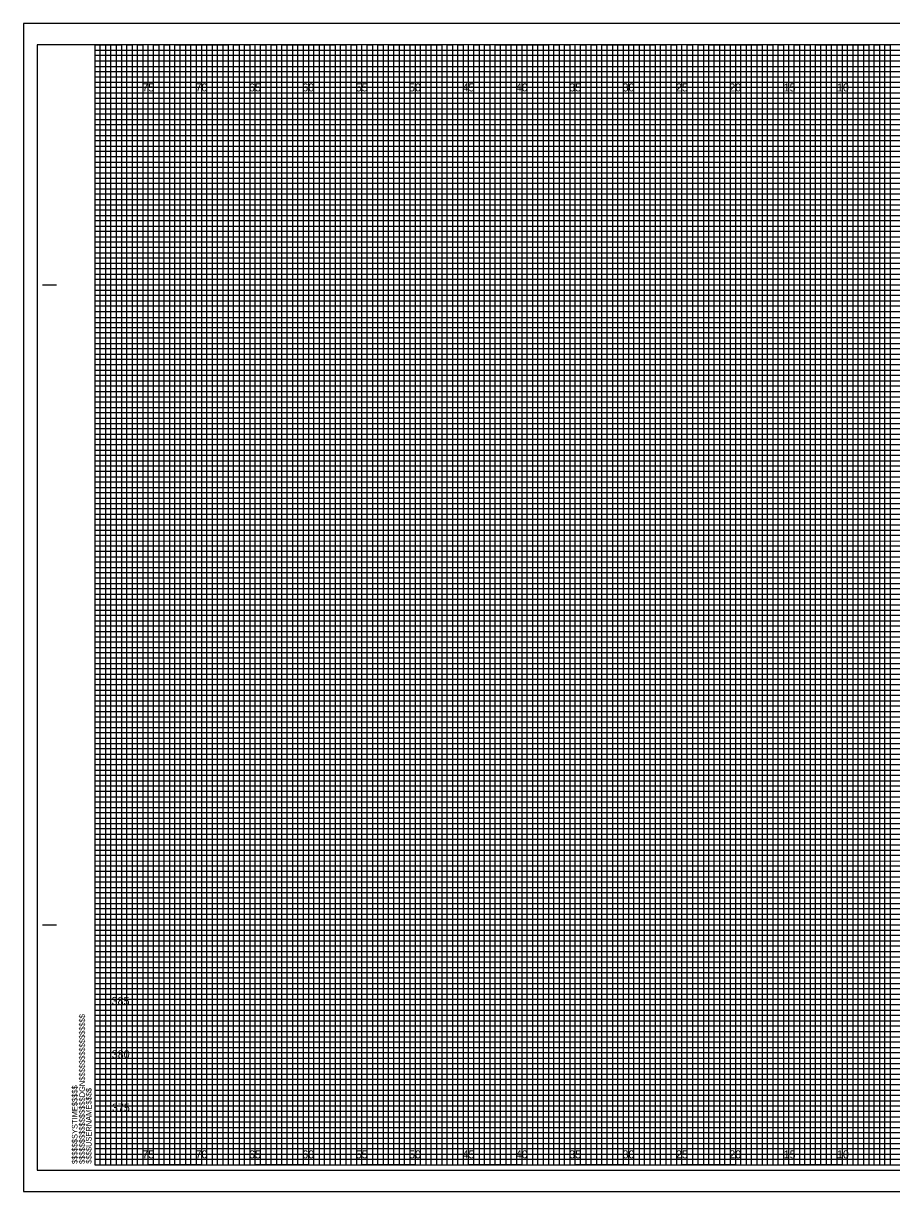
# Model space of a CAD drawing. Extents: x -7 to 162, y -2 to 217.
# Drawn here: x -6.7 to 74.6, y 107.5 to 217 of the extents above; entities that cross this region are included whole.
import ezdxf

# ---------------------------------------------------------------- set-up
doc = ezdxf.new("R2010")
doc.units = 0
for name, color, linetype in [('Exist Cross Section Cell', 7, 'Continuous'), ('Prop CMT Pvmt Course 1', 7, 'Continuous'), ('Prop CMT Pvmt Course 3', 7, 'Continuous'), ('Prop CMT Shld Paved Course 1', 7, 'Continuous'), ('Prop CMT Shld Paved Course 2', 7, 'Continuous'), ('Prop CMT Shld Paved Course 3', 7, 'Continuous'), ('Prop CMT Slope Grass', 7, 'Continuous'), ('Prop CMT Subgrade Earthwork', 7, 'Continuous'), ('Scratch_Level_3', 7, 'Continuous')]:
    doc.layers.add(name, color=color, linetype=linetype)

msp = doc.modelspace()

# ---------------------------------------------------------------- linework, layer by layer
at = {"layer": 'Prop CMT Pvmt Course 3'}
msp.add_lwpolyline([(-6.7, 107.5), (161.65, 107.5), (161.65, 217), (-6.7, 217)], close=True, dxfattribs=at)
at = {"layer": 'Prop CMT Shld Paved Course 1'}
for p, q in [((0, 214.5), (110.95, 214.5)), ((110.95, 213.99), (0, 213.99)), ((0, 213.99), (0, 213.5)), ((0, 213.5), (110.95, 213.5)), ((110.95, 212.94), (0, 212.94)), ((0, 212.94), (0, 212)), ((0, 212), (160, 212))]:
    msp.add_line(p, q, dxfattribs=at)
for points in [[(0, 211.5), (135, 211.5), (160, 211.5)], [(160, 211), (0, 211)], [(0, 210.5), (160, 210.5)], [(160, 209.5), (0, 209.5)], [(0, 209), (160, 209)], [(160, 208.5), (0, 208.49)], [(0, 208), (160, 208)], [(160, 207), (0, 207)], [(0, 206.5), (160, 206.5), (160, 206), (0, 206)], [(0, 205.5), (160, 205.5), (160, 204.5), (0, 204.5)], [(0, 204), (160, 204), (160, 203.5), (0, 203.5)], [(0, 203), (160, 203), (160, 202), (0, 202)], [(0, 201.5), (160, 201.5), (160, 201), (0, 201)], [(0, 200.5), (160, 200.5), (160, 199.5), (0, 199.5)], [(0, 199), (160, 199), (160, 198.5), (0, 198.5)], [(0, 198), (160, 198), (160, 196.97), (160, 196.5), (160, 196), (0, 196)], [(0, 197), (160, 197), (160, 196.5), (0, 196.5)], [(0, 195.5), (160, 195.5), (160, 194.5), (0, 194.51)], [(0, 194.51), (160, 194.5), (160, 194), (0, 194)], [(0, 193.5), (160, 193.5), (160, 193), (0, 193)], [(0, 192), (160, 192), (160, 191.5), (0, 191.5)], [(0, 191), (160, 191), (160, 190.5), (0, 190.5)], [(-0.04, 189.44), (160, 189.44), (160, 188.94), (-0.04, 188.94)], [(0, 188.5), (160, 188.5), (160, 188), (0, 188)], [(0, 187), (160, 187), (160, 186.5), (0, 186.5)], [(0, 186), (160, 186), (160, 185.5), (0, 185.5)], [(0, 184.5), (160, 184.5), (160, 184), (0, 184)], [(0, 183.5), (160, 183.5), (160, 183), (0, 183)], [(0, 182), (160, 182), (160, 181.5), (0, 181.5)], [(0, 181), (160, 181), (160, 180.5), (0, 180.5)], [(0, 179.5), (160, 179.5), (159.99, 178.99), (0, 179)], [(0, 178.5), (160, 178.5), (160, 178), (0, 178)], [(0, 177), (160, 177), (160, 176.5), (0, 176.5)], [(0, 176), (160, 176), (160, 175.5), (0, 175.5)], [(0, 174.5), (160, 174.5), (160, 174), (0, 174)], [(0, 173.5), (160, 173.5), (160, 173), (0, 173)], [(0, 172), (160, 172), (160, 171.5), (0, 171.5)], [(0, 171), (160, 171), (160, 170.5), (0, 170.5)], [(0, 169.5), (160, 169.5), (160, 169), (0, 169)], [(0, 168.5), (160.03, 168.45), (160, 168), (0, 168)], [(0, 167), (160, 167), (160, 166.5), (0, 166.5)], [(0, 166), (160, 166), (160, 165.5), (0, 165.5)], [(0, 164.5), (160, 164.5), (160, 164), (0, 164)], [(0, 163.5), (160, 163.5), (160, 163), (0, 163)], [(0, 162), (160, 162), (160, 161.5), (0, 161.5)], [(0, 161), (160, 161), (160, 160.5), (0, 160.5)], [(0, 159.5), (160, 159.5), (160, 159), (0, 159)], [(0, 158.5), (160, 158.5), (160, 158), (0, 158)], [(0, 157), (160, 157), (160, 156.5), (0, 156.5)], [(0, 156), (160, 156), (160, 155.5), (0, 155.5)], [(0, 154.5), (160, 154.5), (160, 154), (0, 154)], [(0, 153.5), (160, 153.5), (160, 153), (0, 153)], [(0, 152), (160, 152), (160, 151.5), (0, 151.5)], [(0, 151), (160, 151), (160, 150.5), (0, 150.5)], [(0, 149.5), (160, 149.5), (159.99, 148.99), (0, 149)], [(0, 148.5), (160, 148.5), (160, 148), (0, 148)], [(0, 147), (160, 147), (160, 146.5), (0, 146.5)], [(0, 146), (160, 146), (160, 145.5), (0, 145.5)], [(0, 144.5), (160, 144.5), (160, 144), (0, 144)], [(0, 143.5), (160, 143.5), (160, 143), (0, 143)], [(0, 142), (160, 142), (160, 141.5), (0, 141.5)], [(0, 141), (160, 141), (160, 140.5), (0, 140.5)], [(0, 139.5), (160, 139.5), (160, 139), (0, 139)], [(0, 138.5), (160.03, 138.46), (160, 138), (0, 138)], [(0, 137), (160, 137), (160, 136.5), (0, 136.5)], [(0, 136), (160, 136), (160, 135.5), (0, 135.5)], [(0, 134.5), (160, 134.5), (160, 134), (0, 134)], [(0, 133.5), (160, 133.5), (160, 133), (0, 133)], [(0, 132), (160, 132), (160, 131.5), (0, 131.5)], [(0, 131), (160, 131), (160, 130.5), (0, 130.5)], [(0, 129.5), (160, 129.5), (160, 129), (0, 129)], [(0, 128.5), (160, 128.5), (160, 128), (0, 128)], [(0, 127), (160, 127), (160, 126.5), (0, 126.5)], [(0, 126), (160, 126), (160, 125.5), (0, 125.5)], [(0, 124.5), (160, 124.5), (160, 124), (0, 124)], [(0, 123.5), (160, 123.5), (160, 123), (0, 123)], [(0, 122), (160, 122), (160, 121.5), (0, 121.5)], [(0, 121), (160, 121), (160, 120.5), (0, 120.5)], [(0, 119.5), (160, 119.5), (160, 119), (0, 119)], [(0, 118.5), (160, 118.5), (160, 118), (0, 118)], [(0, 117), (160, 117), (160, 116.5), (0, 116.5)], [(0, 116), (160, 116), (160, 115.5), (0, 115.5)], [(0, 114.5), (160, 114.5), (160, 114), (0, 114)], [(0, 113.5), (160, 113.5), (160, 113), (0, 113)], [(0, 112), (160, 112), (160, 111.5), (0, 111.5)], [(0, 111), (160, 111), (160, 110.5), (0, 110.5)]]:
    msp.add_lwpolyline(points, dxfattribs=at)
at = {"layer": 'Prop CMT Shld Paved Course 2'}
for p, q in [((-4.9, 192.5), (-3.65, 192.5)), ((-4.85, 192.5), (-3.6, 192.5)), ((-4.9, 132.5), (-3.65, 132.5)), ((-4.85, 132.5), (-3.6, 132.5)), ((0, 110), (0, 110)), ((0, 110), (0, 110)), ((0, 110), (0, 110)), ((0, 110), (0, 110)), ((0, 110), (0, 110)), ((0, 110), (0, 110)), ((0, 110), (0, 110))]:
    msp.add_line(p, q, dxfattribs=at)
msp.add_lwpolyline([(160, 215), (0, 215), (0, 110), (160, 110)], close=True, dxfattribs=at)
at = {"layer": 'Prop CMT Shld Paved Course 3'}
for points in [[(0, 110), (0.5, 110), (0.5, 215), (1, 215), (1, 110)], [(1, 110), (1.5, 110), (1.5, 215), (2, 215), (2, 110)], [(2.5, 110), (3, 110), (3, 215), (3.5, 215), (3.5, 110)], [(3.5, 110), (4, 110), (4, 215), (4.5, 215), (4.5, 110)], [(5, 110), (5.5, 110), (5.5, 215), (6, 215), (6, 110)], [(6, 110), (6.5, 110), (6.5, 215), (7, 215), (7, 110)], [(7.5, 110), (8, 110), (8, 215), (8.5, 215), (8.5, 110)], [(8.5, 110), (9, 110), (9, 215), (9.5, 215), (9.5, 110)], [(10, 110), (10.5, 110), (10.5, 215), (11, 215), (11, 110)], [(11, 110), (11.5, 110), (11.5, 215), (12, 215), (12, 110)], [(12.5, 110), (13, 110), (13, 215), (13.5, 215), (13.5, 110)], [(13.5, 110), (14, 110), (14, 215), (14.5, 215), (14.5, 110)], [(15, 110), (15.5, 110), (15.5, 215), (16, 215), (16, 110)], [(16, 110), (16.5, 110), (16.5, 215), (17, 215), (17, 110)], [(17.5, 110), (18, 110), (18, 215), (18.5, 215), (18.5, 110)], [(18.5, 110), (19, 110), (19, 215), (19.5, 215), (19.5, 110)], [(20, 110), (20.5, 110), (20.5, 215), (21, 215), (21, 110)], [(21, 110), (21.5, 110), (21.5, 215), (22, 215), (22, 110)], [(22.5, 110), (23, 110), (23, 215), (23.5, 215), (23.5, 110)], [(23.5, 110), (24, 110), (24, 215), (24.5, 215), (24.5, 110)], [(25, 110), (25.5, 110), (25.5, 215), (26, 215), (26, 110)], [(26, 110), (26.5, 110), (26.5, 215), (27, 215), (27, 110)], [(27.5, 110), (28, 110), (28, 215), (28.5, 215), (28.5, 110)], [(28.5, 110), (29, 110), (29, 215), (29.5, 215), (29.5, 110)], [(30, 110), (30.5, 110), (30.5, 215), (31, 215), (31, 110)], [(31, 110), (31.5, 110), (31.5, 215), (32, 215), (32, 110)], [(32.5, 110), (33, 110), (33, 215), (33.5, 215), (33.5, 110)], [(33.5, 110), (34, 110), (34, 215), (34.5, 215), (34.5, 110)], [(35, 110), (35.5, 110), (35.5, 215), (36, 215), (36, 110)], [(36, 110), (36.5, 110), (36.5, 215), (37, 215), (37, 110)], [(37.5, 110), (38, 110), (38, 215), (38.5, 215), (38.5, 110)], [(38.5, 110), (39, 110), (39, 215), (39.5, 215), (39.5, 110)], [(40, 110), (40.5, 110), (40.5, 215), (41, 215), (41, 110)], [(41, 110), (41.5, 110), (41.5, 215), (42, 215), (42, 110)], [(42.5, 110), (43, 110), (43, 215), (43.5, 215), (43.5, 110)], [(43.5, 110), (44, 110), (44, 215), (44.5, 215), (44.5, 110)], [(45, 110), (45.5, 110), (45.5, 215), (46, 215), (46, 110)], [(46, 110), (46.5, 110), (46.5, 215), (47, 215), (47, 110)], [(47.5, 110), (48, 110), (48, 215), (48.5, 215), (48.5, 110)], [(48.5, 110), (49, 110), (49, 215), (49.5, 215), (49.5, 110)], [(50, 110), (50.5, 110), (50.5, 215), (51, 215), (51, 110)], [(51, 110), (51.5, 110), (51.5, 215), (52, 215), (52, 110)], [(52.5, 110), (53, 110), (53, 215), (53.5, 215), (53.5, 110)], [(53.5, 110), (54, 110), (54, 215), (54.5, 215), (54.5, 110)], [(55, 110), (55.5, 110), (55.5, 215), (56, 215), (56, 110)], [(56, 110), (56.5, 110), (56.5, 215), (57, 215), (57, 110)], [(57.5, 110), (58, 110), (58, 215), (58.5, 215), (58.5, 110)], [(58.5, 110), (59, 110), (59, 215), (59.5, 215), (59.5, 110)], [(60, 110), (60.5, 110), (60.5, 215), (61, 215), (61, 110)], [(61, 110), (61.5, 110), (61.5, 215), (62, 215), (62, 110)], [(62.5, 110), (63, 110), (63, 215), (63.5, 215), (63.5, 110)], [(63.5, 110), (64, 110), (64, 215), (64.5, 215), (64.5, 110)], [(65, 110), (65.5, 110), (65.5, 215), (66, 215), (66, 110)], [(66, 110), (66.5, 110), (66.5, 215), (67, 215), (67, 110)], [(67.5, 110), (68, 110), (68, 215), (68.5, 215), (68.5, 110)], [(68.5, 110), (69, 110), (69, 215), (69.5, 215), (69.5, 110)], [(70, 110), (70.5, 110), (70.5, 215), (71, 215), (71, 110)], [(71, 110), (71.5, 110), (71.5, 215), (72, 215), (72, 110)], [(72.5, 110), (73, 110), (73, 215), (73.5, 215), (73.5, 110)], [(73.5, 110), (74, 110), (74, 215), (74.5, 215), (74.5, 110)]]:
    msp.add_lwpolyline(points, dxfattribs=at)
at = {"layer": 'Prop CMT Slope Grass'}
for points in [[(0, 215), (2.5, 215), (2.5, 110), (7.5, 110), (7.5, 215), (12.5, 215), (12.5, 110), (17.5, 110), (17.5, 215), (22.5, 215), (22.5, 110), (27.5, 110), (27.5, 215), (32.5, 215), (32.5, 110), (37.5, 110), (37.5, 215), (42.5, 215), (42.5, 110), (47.5, 110), (47.5, 215), (52.5, 215), (52.5, 110), (57.5, 110), (57.5, 215), (62.5, 215), (62.5, 110), (67.5, 110), (67.5, 215), (72.5, 215), (72.5, 110), (77.5, 110)], [(0, 212.5), (137.5, 212.5)], [(0, 202.5), (160, 202.5), (160, 212.5)], [(160, 207.5), (0, 207.5)], [(0, 192.5), (160, 192.5), (160, 197.5), (0, 197.5)], [(0, 182.5), (160, 182.5), (160, 187.5), (0, 187.5)], [(0, 172.5), (160, 172.5), (160, 177.5), (0, 177.5)], [(0, 162.5), (160, 162.5), (160, 167.5), (0, 167.5)], [(0, 152.5), (160, 152.5), (160, 157.5), (0, 157.5)], [(0, 142.5), (160, 142.5), (160, 147.5), (0, 147.5)], [(0, 132.5), (160, 132.5), (160, 137.5), (0, 137.5)], [(0, 122.5), (160, 122.5), (160, 127.5), (0, 127.5)], [(0, 112.5), (160, 112.5), (160, 117.5), (0, 117.5)]]:
    msp.add_lwpolyline(points, dxfattribs=at)
at = {"layer": 'Prop CMT Subgrade Earthwork'}
msp.add_lwpolyline([(-5.4, 109.5), (161.2, 109.5), (161.2, 215), (-5.4, 215)], close=True, dxfattribs=at)
at = {"layer": 'Scratch_Level_3'}
for p, q in [((5, 215), (0, 215)), ((5, 110), (5, 215)), ((15, 215), (10, 215)), ((10, 215), (10, 110)), ((15, 110), (15, 215)), ((25, 215), (20, 215)), ((20, 215), (20, 110)), ((25, 110), (25, 215)), ((35, 215), (30, 215)), ((30, 215), (30, 110)), ((35, 110), (35, 215)), ((45, 215), (40, 215)), ((40, 215), (40, 110)), ((45, 110), (45, 215)), ((55, 215), (50, 215)), ((50, 215), (50, 110)), ((55, 110), (55, 215)), ((65, 215), (60, 215)), ((60, 215), (60, 110)), ((65, 110), (65, 215)), ((75, 215), (70, 215)), ((70, 215), (70, 110)), ((10, 110), (5, 110)), ((20, 110), (15, 110)), ((30, 110), (25, 110)), ((40, 110), (35, 110)), ((50, 110), (45, 110)), ((60, 110), (55, 110)), ((70, 110), (65, 110))]:
    msp.add_line(p, q, dxfattribs=at)
for points in [[(160, 212.5), (160, 205), (0, 205)], [(0, 210), (160, 210)], [(0, 200), (160, 200), (160, 195), (0, 195)], [(0, 190), (160, 190), (160, 185), (0, 185)], [(0, 180), (160, 180), (160, 175), (0, 175)], [(0, 170), (160, 170), (160, 165), (0, 165)], [(0, 160), (160, 160), (160, 155), (0, 155)], [(0, 150), (160, 150), (160, 145), (0, 145)], [(0, 140), (160, 140), (160, 135), (0, 135)], [(0, 130), (160, 130), (160, 125), (0, 125)], [(0, 120), (160, 120), (160, 115), (0, 115)]]:
    msp.add_lwpolyline(points, dxfattribs=at)

# ---------------------------------------------------------------- texts
at = {"layer": 'Exist Cross Section Cell'}
for s, p in [('75', (4.44, 210.62)), ('70', (9.43, 210.62)), ('65', (14.44, 210.62)), ('60', (19.43, 210.62)), ('55', (24.44, 210.62)), ('50', (29.43, 210.62)), ('45', (34.44, 210.62)), ('40', (39.43, 210.62)), ('35', (44.44, 210.62)), ('30', (49.43, 210.62)), ('25', (54.44, 210.62)), ('20', (59.43, 210.62)), ('15', (64.53, 210.62)), ('10', (69.52, 210.62)), ('75', (4.44, 110.62)), ('70', (9.43, 110.62)), ('65', (14.44, 110.62)), ('60', (19.43, 110.62)), ('55', (24.44, 110.62)), ('50', (29.43, 110.62)), ('45', (34.44, 110.62)), ('40', (39.43, 110.62)), ('35', (44.44, 110.62)), ('30', (49.43, 110.62)), ('25', (54.44, 110.62)), ('20', (59.43, 110.62)), ('15', (64.53, 110.62)), ('10', (69.52, 110.62))]:
    msp.add_text(s, height=0.75, dxfattribs=at).set_placement(p)
at = {"layer": 'Prop CMT Pvmt Course 1'}
for s, p in [('385', (1.57, 125)), ('380', (1.58, 120)), ('375', (1.6, 115))]:
    msp.add_text(s, height=0.75, dxfattribs=at).set_placement(p)
at = {"layer": 'Prop CMT Shld Paved Course 2'}
for s, p in [('$$$$$$$$$$$$$$$$DGN$$$$$$$$$$$$$$$$', (-0.94, 110.09)), ('$$$$$$SYSTIME$$$$$', (-1.63, 110.09)), ('$$$$USERNAME$$$$', (-0.31, 110.12))]:
    msp.add_text(s, height=0.525, rotation=90, dxfattribs=at).set_placement(p)

doc.saveas('drawing.dxf')
